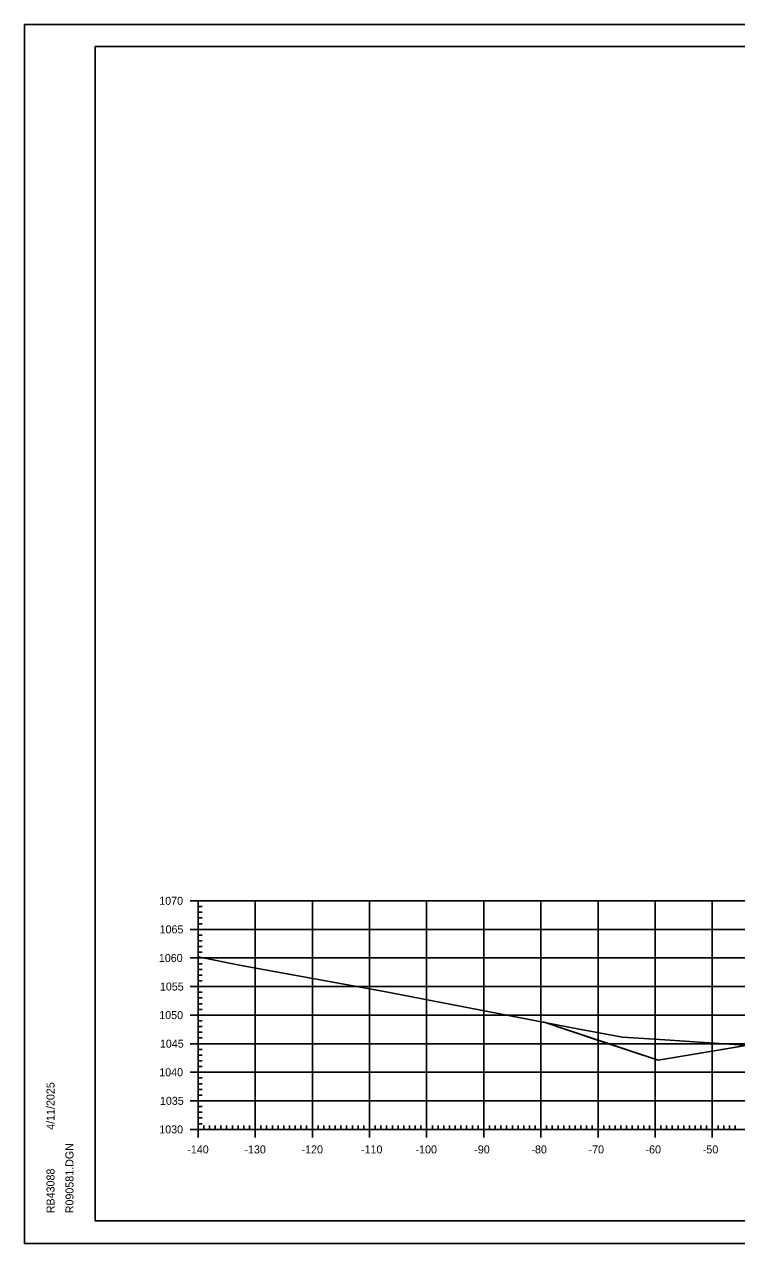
# Model space of a CAD drawing. Extents: x 1322838 to 1324533, y 339903 to 351025.
# Drawn here: x 1323982.8 to 1324107.5, y 345572 to 345785.3 of the extents above; entities that cross this region are included whole.
import ezdxf

# ---------------------------------------------------------------- set-up
doc = ezdxf.new("R2010")
doc.units = 0
for name, color, linetype in [('R_Alt Surface', 7, 'Continuous'), ('R_Axis', 7, 'Continuous'), ('R_Axis Annot', 7, 'Continuous'), ('R_Border', 7, 'Continuous'), ('R_Exist Surface', 7, 'Continuous'), ('R_Fin Surface', 7, 'Continuous'), ('R_Grid', 7, 'Continuous'), ('R_No Plot', 7, 'Continuous')]:
    doc.layers.add(name, color=color, linetype=linetype)

msp = doc.modelspace()

# ---------------------------------------------------------------- linework, layer by layer
at = {"layer": 'R_Alt Surface'}
msp.add_lwpolyline([(1324115.74, 345607.74), (1324093.74, 345604.08), (1324073.62, 345610.78)], dxfattribs=at)
at = {"layer": 'R_Axis'}
for p, q in [((1324011.84, 345631.97), (1324014.64, 345631.97)), ((1324013.24, 345591.97), (1324013.24, 345631.97)), ((1324013.24, 345630.97), (1324013.94, 345630.97)), ((1324013.24, 345629.97), (1324013.94, 345629.97)), ((1324013.24, 345628.97), (1324013.94, 345628.97)), ((1324011.84, 345626.97), (1324014.64, 345626.97)), ((1324013.24, 345627.97), (1324013.94, 345627.97)), ((1324013.24, 345625.97), (1324013.94, 345625.97)), ((1324013.24, 345624.97), (1324013.94, 345624.97)), ((1324011.84, 345621.97), (1324014.64, 345621.97)), ((1324013.24, 345623.97), (1324013.94, 345623.97)), ((1324013.24, 345622.97), (1324013.94, 345622.97)), ((1324013.24, 345620.97), (1324013.94, 345620.97)), ((1324013.24, 345619.97), (1324013.94, 345619.97)), ((1324013.24, 345618.97), (1324013.94, 345618.97)), ((1324013.24, 345617.97), (1324013.94, 345617.97)), ((1324011.84, 345616.97), (1324014.64, 345616.97)), ((1324013.24, 345615.97), (1324013.94, 345615.97)), ((1324013.24, 345614.97), (1324013.94, 345614.97)), ((1324013.24, 345613.97), (1324013.94, 345613.97)), ((1324011.84, 345611.97), (1324014.64, 345611.97)), ((1324013.24, 345612.97), (1324013.94, 345612.97)), ((1324013.24, 345610.97), (1324013.94, 345610.97)), ((1324013.24, 345609.97), (1324013.94, 345609.97)), ((1324011.84, 345606.97), (1324014.64, 345606.97)), ((1324013.24, 345608.97), (1324013.94, 345608.97)), ((1324013.24, 345607.97), (1324013.94, 345607.97)), ((1324013.24, 345605.97), (1324013.94, 345605.97)), ((1324013.24, 345604.97), (1324013.94, 345604.97)), ((1324013.24, 345603.97), (1324013.94, 345603.97)), ((1324013.24, 345602.97), (1324013.94, 345602.97)), ((1324011.84, 345601.97), (1324014.64, 345601.97)), ((1324013.24, 345600.97), (1324013.94, 345600.97)), ((1324013.24, 345599.97), (1324013.94, 345599.97)), ((1324013.24, 345598.97), (1324013.94, 345598.97)), ((1324011.84, 345596.97), (1324014.64, 345596.97)), ((1324013.24, 345597.97), (1324013.94, 345597.97)), ((1324013.24, 345595.97), (1324013.94, 345595.97)), ((1324013.24, 345594.97), (1324013.94, 345594.97)), ((1324013.24, 345593.97), (1324013.94, 345593.97)), ((1324013.24, 345590.57), (1324013.24, 345593.37)), ((1324013.24, 345592.97), (1324013.94, 345592.97)), ((1324014.24, 345591.97), (1324014.24, 345592.67)), ((1324015.24, 345591.97), (1324015.24, 345592.67)), ((1324016.24, 345591.97), (1324016.24, 345592.67)), ((1324017.24, 345591.97), (1324017.24, 345592.67)), ((1324018.24, 345591.97), (1324018.24, 345592.67)), ((1324019.24, 345591.97), (1324019.24, 345592.67)), ((1324020.24, 345591.97), (1324020.24, 345592.67)), ((1324021.24, 345591.97), (1324021.24, 345592.67)), ((1324022.24, 345591.97), (1324022.24, 345592.67)), ((1324023.24, 345590.57), (1324023.24, 345593.37)), ((1324024.24, 345591.97), (1324024.24, 345592.67)), ((1324025.24, 345591.97), (1324025.24, 345592.67)), ((1324026.24, 345591.97), (1324026.24, 345592.67)), ((1324027.24, 345591.97), (1324027.24, 345592.67)), ((1324028.24, 345591.97), (1324028.24, 345592.67)), ((1324029.24, 345591.97), (1324029.24, 345592.67)), ((1324030.24, 345591.97), (1324030.24, 345592.67)), ((1324031.24, 345591.97), (1324031.24, 345592.67)), ((1324032.24, 345591.97), (1324032.24, 345592.67)), ((1324033.24, 345590.57), (1324033.24, 345593.37)), ((1324034.24, 345591.97), (1324034.24, 345592.67)), ((1324035.24, 345591.97), (1324035.24, 345592.67)), ((1324036.24, 345591.97), (1324036.24, 345592.67)), ((1324037.24, 345591.97), (1324037.24, 345592.67)), ((1324038.24, 345591.97), (1324038.24, 345592.67)), ((1324039.24, 345591.97), (1324039.24, 345592.67)), ((1324040.24, 345591.97), (1324040.24, 345592.67)), ((1324041.24, 345591.97), (1324041.24, 345592.67)), ((1324042.24, 345591.97), (1324042.24, 345592.67)), ((1324043.24, 345590.57), (1324043.24, 345593.37)), ((1324044.24, 345591.97), (1324044.24, 345592.67)), ((1324045.24, 345591.97), (1324045.24, 345592.67)), ((1324046.24, 345591.97), (1324046.24, 345592.67)), ((1324047.24, 345591.97), (1324047.24, 345592.67)), ((1324048.24, 345591.97), (1324048.24, 345592.67)), ((1324049.24, 345591.97), (1324049.24, 345592.67)), ((1324050.24, 345591.97), (1324050.24, 345592.67)), ((1324051.24, 345591.97), (1324051.24, 345592.67)), ((1324052.24, 345591.97), (1324052.24, 345592.67)), ((1324053.24, 345590.57), (1324053.24, 345593.37)), ((1324054.24, 345591.97), (1324054.24, 345592.67)), ((1324055.24, 345591.97), (1324055.24, 345592.67)), ((1324056.24, 345591.97), (1324056.24, 345592.67)), ((1324057.24, 345591.97), (1324057.24, 345592.67)), ((1324058.24, 345591.97), (1324058.24, 345592.67)), ((1324059.24, 345591.97), (1324059.24, 345592.67)), ((1324060.24, 345591.97), (1324060.24, 345592.67)), ((1324061.24, 345591.97), (1324061.24, 345592.67)), ((1324062.24, 345591.97), (1324062.24, 345592.67)), ((1324063.24, 345590.57), (1324063.24, 345593.37)), ((1324064.24, 345591.97), (1324064.24, 345592.67)), ((1324065.24, 345591.97), (1324065.24, 345592.67)), ((1324066.24, 345591.97), (1324066.24, 345592.67)), ((1324067.24, 345591.97), (1324067.24, 345592.67)), ((1324068.24, 345591.97), (1324068.24, 345592.67)), ((1324069.24, 345591.97), (1324069.24, 345592.67)), ((1324070.24, 345591.97), (1324070.24, 345592.67)), ((1324071.24, 345591.97), (1324071.24, 345592.67)), ((1324072.24, 345591.97), (1324072.24, 345592.67)), ((1324073.24, 345590.57), (1324073.24, 345593.37)), ((1324074.24, 345591.97), (1324074.24, 345592.67)), ((1324075.24, 345591.97), (1324075.24, 345592.67)), ((1324076.24, 345591.97), (1324076.24, 345592.67)), ((1324077.24, 345591.97), (1324077.24, 345592.67)), ((1324078.24, 345591.97), (1324078.24, 345592.67)), ((1324079.24, 345591.97), (1324079.24, 345592.67)), ((1324080.24, 345591.97), (1324080.24, 345592.67)), ((1324081.24, 345591.97), (1324081.24, 345592.67)), ((1324082.24, 345591.97), (1324082.24, 345592.67)), ((1324083.24, 345590.57), (1324083.24, 345593.37)), ((1324084.24, 345591.97), (1324084.24, 345592.67)), ((1324085.24, 345591.97), (1324085.24, 345592.67)), ((1324086.24, 345591.97), (1324086.24, 345592.67)), ((1324087.24, 345591.97), (1324087.24, 345592.67)), ((1324088.24, 345591.97), (1324088.24, 345592.67)), ((1324089.24, 345591.97), (1324089.24, 345592.67)), ((1324090.24, 345591.97), (1324090.24, 345592.67)), ((1324091.24, 345591.97), (1324091.24, 345592.67)), ((1324092.24, 345591.97), (1324092.24, 345592.67)), ((1324093.24, 345590.57), (1324093.24, 345593.37)), ((1324094.24, 345591.97), (1324094.24, 345592.67)), ((1324095.24, 345591.97), (1324095.24, 345592.67)), ((1324096.24, 345591.97), (1324096.24, 345592.67)), ((1324097.24, 345591.97), (1324097.24, 345592.67)), ((1324098.24, 345591.97), (1324098.24, 345592.67)), ((1324099.24, 345591.97), (1324099.24, 345592.67)), ((1324100.24, 345591.97), (1324100.24, 345592.67)), ((1324101.24, 345591.97), (1324101.24, 345592.67)), ((1324102.24, 345591.97), (1324102.24, 345592.67)), ((1324103.24, 345590.57), (1324103.24, 345593.37)), ((1324104.24, 345591.97), (1324104.24, 345592.67)), ((1324105.24, 345591.97), (1324105.24, 345592.67)), ((1324106.24, 345591.97), (1324106.24, 345592.67)), ((1324107.24, 345591.97), (1324107.24, 345592.67)), ((1324011.84, 345591.97), (1324014.64, 345591.97)), ((1324013.24, 345591.97), (1324293.24, 345591.97))]:
    msp.add_line(p, q, dxfattribs=at)
at = {"layer": 'R_Border'}
for p, q in [((1323995.24, 345781.43), (1324311.42, 345781.43)), ((1323995.24, 345575.97), (1323995.24, 345781.43)), ((1323995.24, 345575.97), (1323995.24, 345575.97)), ((1324311.42, 345575.97), (1323995.24, 345575.97))]:
    msp.add_line(p, q, dxfattribs=at)
at = {"layer": 'R_Exist Surface'}
msp.add_lwpolyline([(1324013.24, 345622.14), (1324020.75, 345620.68), (1324045.53, 345616.15), (1324079.62, 345609.57), (1324087.53, 345608.12), (1324094.94, 345607.62), (1324114, 345606.36)], dxfattribs=at)
at = {"layer": 'R_Fin Surface'}
msp.add_lwpolyline([(1324073.62, 345610.78), (1324083.85, 345607.38), (1324093.74, 345604.08), (1324100.75, 345605.24), (1324107.75, 345606.41)], dxfattribs=at)
at = {"layer": 'R_Grid'}
for p, q in [((1324013.24, 345631.97), (1324293.24, 345631.97)), ((1324013.24, 345591.97), (1324013.24, 345631.97)), ((1324023.24, 345591.97), (1324023.24, 345631.97)), ((1324033.24, 345591.97), (1324033.24, 345631.97)), ((1324043.24, 345591.97), (1324043.24, 345631.97)), ((1324053.24, 345591.97), (1324053.24, 345631.97)), ((1324063.24, 345591.97), (1324063.24, 345631.97)), ((1324073.24, 345591.97), (1324073.24, 345631.97)), ((1324083.24, 345591.97), (1324083.24, 345631.97)), ((1324093.24, 345591.97), (1324093.24, 345631.97)), ((1324103.24, 345591.97), (1324103.24, 345631.97)), ((1324013.24, 345626.97), (1324293.24, 345626.97)), ((1324013.24, 345621.97), (1324293.24, 345621.97)), ((1324013.24, 345616.97), (1324293.24, 345616.97)), ((1324013.24, 345611.97), (1324293.24, 345611.97)), ((1324013.24, 345606.97), (1324293.24, 345606.97)), ((1324013.24, 345601.97), (1324293.24, 345601.97)), ((1324013.24, 345596.97), (1324293.24, 345596.97)), ((1324013.24, 345591.97), (1324293.24, 345591.97))]:
    msp.add_line(p, q, dxfattribs=at)
at = {"layer": 'R_No Plot'}
for p, q in [((1323982.84, 345785.33), (1324316.17, 345785.33)), ((1323982.84, 345571.99), (1324316.17, 345571.99))]:
    msp.add_line(p, q, dxfattribs=at)
for points in [[(1323982.83, 345785.33), (1324316.17, 345785.33), (1324316.17, 345571.99), (1323982.83, 345571.99)], [(1324229.16, 345781.43), (1324248.78, 345781.43), (1324248.78, 345771.55), (1324264.89, 345771.55), (1324288.09, 345771.55), (1324288.21, 345743.39), (1324311.42, 345743.39), (1324311.42, 345575.97), (1323995.24, 345575.97), (1323995.24, 345781.43)]]:
    msp.add_lwpolyline(points, close=True, dxfattribs=at)

# ---------------------------------------------------------------- texts
at = {"layer": 'R_Axis Annot'}
for s, p in [('1070', (1324006.44, 345631.27)), ('1065', (1324006.5, 345626.27)), ('1060', (1324006.37, 345621.27)), ('1055', (1324006.56, 345616.27)), ('1050', (1324006.44, 345611.27)), ('1045', (1324006.56, 345606.27)), ('1040', (1324006.44, 345601.27)), ('1035', (1324006.56, 345596.27)), ('1030', (1324006.44, 345591.27)), ('-140', (1324011.35, 345587.77)), ('-130', (1324021.35, 345587.77)), ('-120', (1324031.35, 345587.77)), ('-110', (1324041.75, 345587.77)), ('-100', (1324051.3, 345587.77)), ('-90', (1324061.58, 345587.77)), ('-80', (1324071.58, 345587.77)), ('-70', (1324081.58, 345587.77)), ('-60', (1324091.55, 345587.77)), ('-50', (1324101.58, 345587.77))]:
    msp.add_text(s, height=1.4, dxfattribs=at).set_placement(p)
at = {"layer": 'R_Border'}
for s, p in [('4/11/2025', (1323988.11, 345591.9)), ('R090581.DGN', (1323991.43, 345577.3)), ('RB43088', (1323988.11, 345577.3))]:
    msp.add_text(s, height=1.4, rotation=90, dxfattribs=at).set_placement(p)

doc.saveas('drawing.dxf')
